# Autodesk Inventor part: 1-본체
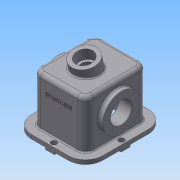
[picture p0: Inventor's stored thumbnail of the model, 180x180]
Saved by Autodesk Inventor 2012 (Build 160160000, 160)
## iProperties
Created: 2014-11
Part Number: 1-본체
Material: 알루미늄-6061
Document SubType Name: Modeling
Designer: User11
Density: 2.71 g/cm^3
Mass: 2881.84 g
Surface Area: 2079.21 cm^2
Volume: 1063.41 cm^3
Author: User11
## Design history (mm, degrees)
sketch "스케치1"
  geometry: L1 (-76, 65)-(76, 65); L2 (76, 65)-(76, -65); L3 (76, -65)-(-76, -65); L4 (-76, -65)-(-76, 65); 3 further points
  constraints: 8 end point, 2 midpoint, 2 parallel, 1 horizontal, 1 horizontal alignment, 1 perpendicular, 1 vertical alignment
  dimensions: "d0" = 130 distance of L3.end L1.start; "d1" = 152 distance of L1.start L1.end
extrude "돌출1" new body sketch "스케치1" distance "d2" = 128; taper "d3" = 0 deg
feature "쉘2" dims "d5" = 10
sketch "스케치6"
  geometry: L1 (77, 60)-(45, 60); L2 (-55, 10)-(-55, 128) reference; L3 (-65, 128)-(65, 128) reference; L4 (77, 34)-(45, 34); L5 (45, 34)-(45, 24.5); L6 (45, 24.5)-(55, 14.5); L7 (55, 14.5)-(77, 14.5); L8 (77, 14.5)-(77, 34); 2 further points
  constraints: 12 end point, 3 parallel, 2 vertical alignment, 1 horizontal, 1 perpendicular
  dimensions: "d6" = 68 distance between parallel lines of L3 L1; "d7" = 32 distance of L1.start L1.end; "d8" = 12 horizontal distance of point (65, 0) L1.start; "d9" = 10 horizontal distance of L5.end L6.end; "d10" = 91 diameter of L7 L1; "d11" = 71 diameter of L5.end L1; "d12" = 52 diameter of L4 L1
revolve "회전1" sketch "스케치6" stored, may be unused: angle "d13" = 90 deg
sketch "스케치7"
  geometry: C1 r 26 at (0, 0) reference; C2 r 26 at (0, 0) reference; 1 further point
extrude "돌출2" cut sketch "스케치7" stored distance "d14" = 118; taper "d15" = 0 deg
sketch "스케치8" dims "d16" = 70
  geometry: C1 r 45.5 at (0, 0) reference; C2 r 26 at (0, 0) reference; 6 further points
  constraints: 2 vertical alignment, 1 coincident, 7 other
  dimensions: "d19" = 360 deg dimension on C1.centre point (0, 35) (derived)
hole "구멍1" sketch "스케치8" at (0, 35), (-35, 0), (0, -35), (35, 0) diameter "d21" = 3.242; stored, may be unused: countersink angle "d25" = 90 deg, drill point angle "d27" = 118 deg; dims "d22" = 13, "d23" = 4, "d24" = 2, "d26" = 16
sketch "스케치9"
  geometry: L1 (76, 65)-(76, -65) reference; L2 (-76, 65)-(76, 65) reference; L3 (-76, -65)-(-76, 65) reference; L4 (76, -65)-(-76, -65) reference; L5 (-98, 87)-(98, 87); L6 (98, 87)-(98, -87); L7 (98, -87)-(-98, -87); L8 (-98, -87)-(-98, 87); 4 further points
  constraints: 8 end point, 3 midpoint, 2 parallel, 1 horizontal, 1 horizontal alignment, 1 perpendicular, 1 vertical alignment
  dimensions: "d28" = 174 distance of L5.end L6.end; "d29" = 196 distance of L5.start L5.end
extrude "돌출3" join sketch "스케치9" distance "d30" = 10; taper "d31" = 0 deg
fillet "모깎기1" dims "d32" = 42
sketch "스케치10"
  geometry: L1 (56, -87)-(-56, -87) reference; L2 (98, 45)-(98, -45) reference; L3 (-56, 87)-(56, 87) reference; L4 (-98, -45)-(-98, 45) reference; L5 (-11, 87)-(11, 87); L6 (11, 87)-(11, 67); L7 (11, 67)-(-11, 67); L8 (-11, 67)-(-11, 87); L9 (-98, 11)-(-78, 11); L10 (-78, 11)-(-78, -11); L11 (-78, -11)-(-98, -11); L12 (-98, -11)-(-98, 11); L13 (-11, -87)-(11, -87); L14 (11, -87)-(11, -67); L15 (11, -67)-(-11, -67); L16 (-11, -67)-(-11, -87); L17 (98, 11)-(78, 11); L18 (78, 11)-(78, -11); L19 (78, -11)-(98, -11); L20 (98, -11)-(98, 11); 5 further points
  constraints: 32 end point, 8 parallel, 5 perpendicular, 4 horizontal, 4 midpoint, 4 point on line, 2 horizontal alignment, 2 vertical alignment
  dimensions: "d33" = 22 distance between parallel lines of L6 L8; "d34" = 20 distance of L5.end L6.end; "d35" = 22 distance of L9.end L10.end; "d36" = 20 distance of L13.end L14.end; "d37" = 22 distance of L14.end L15.end; "d38" = 20 distance of L17.start L17.end; "d39" = 22 distance of L17.end L18.end
extrude "돌출4" join sketch "스케치10" distance "d40" = 5; taper "d41" = 0 deg
sketch "스케치11"
  geometry: L1 (11, 67)-(-11, 67) reference; L2 (11, 87)-(11, 67) reference; L3 (-11, -67)-(11, -67) reference; L4 (-78, 11)-(-78, -11) reference; L5 (78, -11)-(78, 11) reference; C1 r 4.5 at (0, 77); C2 r 4.5 at (-88, 0); C3 r 4.5 at (0, -77); C4 r 4.5 at (88, 0); 1 further point
  constraints: 4 centre point, 3 equal radius, 2 horizontal alignment, 1 vertical alignment
  dimensions: "d42" = 10 distance from line of L1 C1.centre; "d43" = 11 distance from line of L2 C1.centre; "d44" = 10 distance from line of L3 C3.centre; "d45" = 10 distance from line of L4 C2.centre; "d46" = 10 distance from line of C4.centre L5; "d47" = 9 diameter of C1
extrude "돌출5" cut sketch "스케치11" distance "d48" = 6.4; taper "d49" = 0 deg
sketch "스케치12"
  geometry: C1 r 4.5 at (0, 0) reference; C2 r 4.5 at (88, 77) reference; C3 r 4.5 at (176, 0) reference; C4 r 4.5 at (88, -77) reference; C5 r 7 at (0, 0); C6 r 7 at (88, 77); C7 r 7 at (176, 0); C8 r 7 at (88, -77); 1 further point
  constraints: 4 centre point, 4 coincident, 3 equal radius
  dimensions: "d50" = 14 diameter of C5
extrude "돌출6" cut sketch "스케치12" distance "d51" = 8.6; taper "d52" = 0 deg
node "작업 평면3"
node "작업 평면4"
node "작업 평면6"
  node "작업 평면5"
fillet "모깎기2" dims "d68" = 20
fillet "모깎기3" dims "d69" = 10
fillet "모깎기4" dims "d70" = 3
fillet "모깎기6" dims "d72" = 10
fillet "모깎기7" dims "d73" = 3
chamfer "모따기1" distance "d74" = 1; stored, may be unused: second distance "d75" = 2, angle "d76" = 45 deg
fillet "모깎기8" dims "d77" = 3
sketch "스케치16"
  geometry: L1 (118, 0)-(118, 34) reference; 2 further points
  constraints: 1 horizontal alignment, 1 other
  dimensions: "d78" = 92 distance from line of L1 point (26, 45)
feature "엠보싱1" sketch "스케치16" dims "d6" = 68, "d7" = 32, "d8" = 12, "d9" = 10, "d10" = 91, "d11" = 71, "d12" = 52, "d79" = 1, "d80" = 0
node "작업 평면11"
node "작업 평면12"
sketch "스케치21"
  geometry: L1 (-45, 64.558)-(45, 64.558) reference; L2 (45, 76.418)-(-45, 76.418) reference; C1 r 31 at (0, 8.418); 1 further point
  constraints: 1 centre point, 1 vertical alignment
  dimensions: "d91" = 68 distance from line of C1.centre L2; "d92" = 62 diameter of C1
extrude "돌출10" join sketch "스케치21" stored distance "d93" = 25; taper "d94" = 0 deg
fillet "모깎기10" dims "d102" = 3
sketch "스케치24"
  geometry: C1 r 21 at (0, 0) reference; C2 r 31 at (0, 0) reference; C3 r 31 at (0, 0); 1 further point
  constraints: 1 centre point, 1 coincident, 1 concentric
extrude "돌출13" join sketch "스케치24" distance "d103" = 3; taper "d104" = 0 deg
sketch "스케치25"
  geometry: C1 r 21 at (0, 0) reference; C2 r 21 at (0, 0); 1 further point
  constraints: 1 centre point, 1 coincident, 1 concentric
extrude "돌출14" join sketch "스케치25" distance "d105" = 3; taper "d106" = 0 deg
sketch "스케치26"
  geometry: C1 r 31 at (0, 0) reference; C2 r 21 at (0, 0); 1 further point
  constraints: 1 centre point, 1 coincident
  dimensions: "d107" = 42 diameter of C2
extrude "돌출15" cut sketch "스케치26" distance "d108" = 25; taper "d109" = 0 deg
sketch "스케치27"
  geometry: C1 r 21 at (0, 0) reference; C2 r 15 at (0, 0); 1 further point
  constraints: 1 centre point, 1 coincident
  dimensions: "d110" = 30 diameter of C2
extrude "돌출16" cut sketch "스케치27" stored distance "d111" = 25; taper "d112" = 0 deg
fillet "모깎기11" dims "d113" = 0.3
node "솔리드1"
mirror "대칭1"
mirror "대칭2"
node "투영된 루프1"
node "투영된 루프2"
node "투영된 루프3"
other parameters: "d55" = 128, "d56" = -68, "d57" = 12 deg, "d58" = 25, "d89" = -25
